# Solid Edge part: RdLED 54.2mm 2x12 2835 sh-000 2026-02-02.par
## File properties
Author: patryk.ciesielski
Template: iso metric part.par
Last saved by: patryk.ciesielski
Revision: 1
Application: Solid Edge
Gęstość: 0.000 kg/m^3
Dokładność: 0.990
Username: patryk.ciesielski
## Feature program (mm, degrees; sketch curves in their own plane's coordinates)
body "unnamed Body 1"
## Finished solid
Body 1: solid body, 1381 faces, 3806 edges, 2536 vertices.
  Faces by surface: plane 964, cylinder 319, spline 64, torus 20, sphere 10, cone 4
  Edges by curve: line 2732, curve on surface 704, circle 312, spline 48, ellipse 10
Bounding box of the edges (mm; curved faces can reach further): 54.200 x 54.200 x 4.300, from (-27.1, -27.1, -1.6) to (27.1, 27.1, 2.7).
Cylindrical faces by radius (mm): R0.0719 x4, R0.094 x8, R0.0943 x8, R0.1 x48, R0.1641 x4, R0.1692 x4, R0.191 x16, R0.2 x32, R0.2277 x8, R0.25 x28, R0.2838 x8, R0.3 x16, R0.35 x36, R0.3811 x4, R0.4 x8, R0.45 x8, R0.5 x24, R0.6 x16, R0.6986 x4, R0.6987 x4, R0.85 x8, R1.0056 x8, R1.025 x2, R1.5 x6, R14.6 x6, R27.1 x1
Conical faces (half-angle, radius in mm at the cone's reference point): 32.2665 deg R0.136 x4
Toroidal faces (ring radius, tube radius in mm): R0.6563 r0.3 x8, R0.665 r0.3204 x4, R0.6668 r0.3223 x4, R1.2 r0.1 x4
Spherical faces by radius (mm): R0.1 x10
Planar faces by outward normal: +x 15, +y 15, +z 149, -x 15, -y 15, -z 77, oblique 678
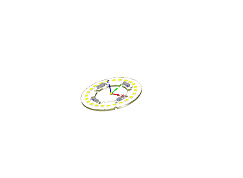
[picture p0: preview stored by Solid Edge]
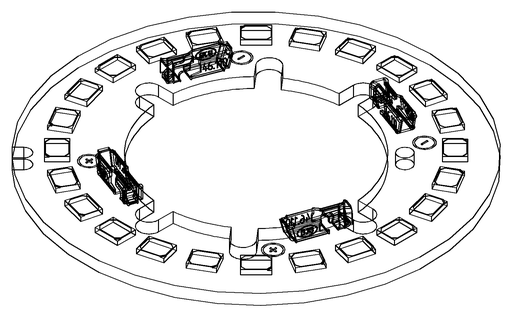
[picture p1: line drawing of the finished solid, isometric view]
